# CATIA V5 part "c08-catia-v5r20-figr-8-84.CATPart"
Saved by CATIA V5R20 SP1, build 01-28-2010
Part number: Part1
Bounding box of the stored display mesh (mm): x -44.701 to 35.128, y -35.23 to 15.392, z -47.191 to 31.322
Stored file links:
  D:\v5_r20\psrt_files_downloaded\c08-catia-v5r20-prt\c08-catia-v5r20-figr-8-84.CATPart
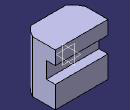
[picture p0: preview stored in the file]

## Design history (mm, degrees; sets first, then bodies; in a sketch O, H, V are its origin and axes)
Body1 (main body)
  Sketch1 on xy-plane, origin (0, 0, 0), H (1, 0, 0), V (0, 1, 0)
    line L1 (-44.7013, 25.8759) -> (35.1284, 25.8759)
    line L2 (35.1284, 25.8759) -> (35.1284, -18.9612)
    line L3 (-44.7013, 25.8759) -> (-44.7013, -18.9612)
    arc A1 centre (-4.7865, 1.0752) radius 44.6615 from (-44.7013, -18.9612) to (35.1284, -18.9612) ccw
    horizontal: L1 H
    vertical: L2 V, L3 V
  Sketch2 on yz-plane, origin (0, 0, 0), H (0, 1, 0), V (0, 0, 1)
    line L1 (-35.2302, 31.3221) -> (-35.2302, -47.1914)
    point P2 (-35.2302, -47.1914)
    point P3 (-35.2302, -47.1914)
    line L2 (-35.2302, -47.1914) -> (15.3919, -47.1914)
    point P4 (15.3919, -47.1914)
    line L3 (15.3919, 31.3221) -> (-35.2302, 31.3221)
    line L4 (15.3919, 31.3221) -> (15.3919, 10.6589)
    line L5 (15.3919, 10.6589) -> (1.7321, 10.6589)
    line L6 (1.7321, 10.6589) -> (1.7321, -13.9018)
    line L7 (1.7321, -13.9018) -> (15.3919, -13.9018)
    point P9 (15.3919, -13.9018)
    line L8 (15.3919, -13.9018) -> (15.3919, -47.1914)
    point P10 (15.3919, -47.1914)
    vertical: L1 V, L4 V, L6 V, L8 V
    horizontal: L2 H, L3 H, L5 H, L7 H
    coincidence: P9 L4, P10 L2, P10 P4, P3 P2
  SolidCombine1: FirstComponentProfile Sketch1, FirstComponentDirection Sketch1, SecondComponentProfile Sketch2, SecondComponentDirection Sketch2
